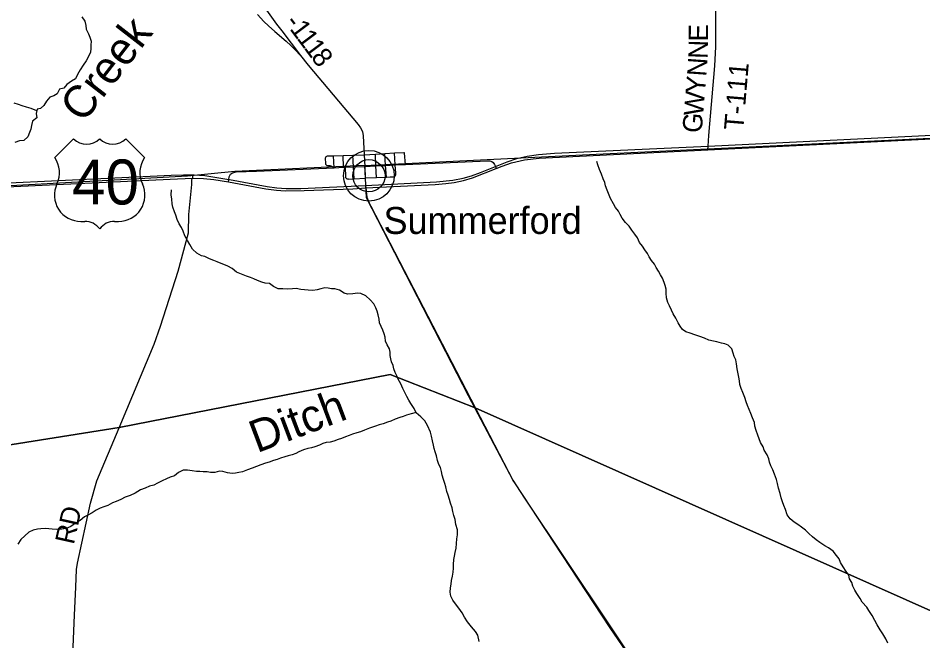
# Model space of a CAD drawing. Extents: x 0 to 36.5, y 0 to 25.3.
# Drawn here: x 3.798 to 6.451, y 15.97 to 17.796 of the extents above; entities that cross this region are included whole.
import ezdxf

# ---------------------------------------------------------------- set-up
doc = ezdxf.new("R2010")
doc.units = 0
for name, color, linetype in [('DV_X_Township_Line', 7, 'Continuous'), ('GM_X_Major_River', 7, 'Continuous'), ('GM_X_Major_River_Text', 7, 'Continuous'), ('GM_X_Minor_River', 7, 'Continuous'), ('GM_X_Minor_River_Text', 7, 'Continuous'), ('GM_X_Rail_Line', 7, 'Continuous'), ('GM_X_State_Route', 7, 'Continuous'), ('GM_X_Township_Road', 7, 'Continuous'), ('GM_X_Township_Road_Text', 7, 'Continuous'), ('GM_X_Unincorporated', 7, 'Continuous'), ('GM_X_Unincorporated_Location', 7, 'Continuous'), ('GM_X_Unincorporated_Text', 7, 'Continuous'), ('GM_X_US_Location', 7, 'Continuous'), ('GM_X_US_Route', 7, 'Continuous'), ('GM_X_US_Shield', 7, 'Continuous'), ('SH_Data', 7, 'Continuous')]:
    doc.layers.add(name, color=color, linetype=linetype)

msp = doc.modelspace()

# ---------------------------------------------------------------- linework, layer by layer
at = {"layer": 'DV_X_Township_Line'}
msp.add_lwpolyline([(4.5783, 20.9), (3.3366, 20.9), (3.2612, 20.6041), (2.8463, 19.037), (2.6265, 18.2595), (2.5271, 17.8912), (2.5226, 17.8751), (2.5165, 17.8524), (2.5144, 17.8445), (2.4192, 17.4891), (2.3437, 17.2326), (2.3403, 17.2198), (2.1039, 16.2931), (2.4938, 16.3413), (4.0938, 16.595), (4.8891, 16.7511), (5.1383, 16.6527), (6.6079, 15.9978)], dxfattribs=at)
msp.add_lwpolyline([(2.1, 16.2788), (2.1, 14.1), (8.9, 14.1), (8.9, 14.8674), (8.5228, 15.0526), (8.0723, 15.2737), (7.8139, 15.4027), (7.7814, 15.4189), (7.7552, 15.432), (7.703, 15.458), (6.8419, 15.8878), (6.6079, 15.9978), (5.1383, 16.6527), (4.8891, 16.7511), (4.0938, 16.595), (2.4938, 16.3413), (2.1039, 16.2931)], close=True, dxfattribs=at)
at = {"layer": 'GM_X_Major_River'}
msp.add_lwpolyline([(3.9844, 17.7994), (3.993, 17.7864), (3.9959, 17.7738), (3.9973, 17.7632), (4.0036, 17.7498), (4.0081, 17.7399), (4.0122, 17.7281), (4.0113, 17.716), (4.0108, 17.7065), (4.0096, 17.6962), (4.0042, 17.6833), (3.9972, 17.6701), (3.988, 17.6576), (3.9795, 17.644), (3.9722, 17.6304), (3.966, 17.6179), (3.9538, 17.6104), (3.9408, 17.601), (3.9316, 17.5905), (3.9194, 17.5872), (3.9117, 17.5732), (3.9022, 17.5679), (3.8908, 17.5635), (3.8804, 17.5522), (3.8731, 17.5397), (3.8632, 17.5306), (3.8533, 17.5284), (3.8505, 17.5163), (3.8527, 17.5034), (3.84, 17.4932), (3.8369, 17.4807), (3.8349, 17.4701), (3.8306, 17.4602), (3.826, 17.4477), (3.8145, 17.4364), (3.8012, 17.4362), (3.7883, 17.4313)], dxfattribs=at)
at = {"layer": 'GM_X_Minor_River'}
for points in [[(3.8523, 17.524), (3.8362, 17.5301), (3.8222, 17.534), (3.8097, 17.5383), (3.7991, 17.5422), (3.7859, 17.5465)], [(6.0244, 16.4315), (6.0214, 16.4425), (6.0155, 16.4586), (6.011, 16.4708), (6.0054, 16.4826), (6.0017, 16.4936), (5.9988, 16.5039), (5.9943, 16.515), (5.9857, 16.5287), (5.9828, 16.5386), (5.9753, 16.5513), (5.9708, 16.5619), (5.9675, 16.573), (5.9619, 16.5867), (5.9582, 16.5997), (5.9568, 16.6096), (5.9512, 16.6241), (5.9468, 16.6359), (5.942, 16.6485), (5.9364, 16.6603), (5.933, 16.671), (5.9286, 16.6832), (5.923, 16.6977), (5.9182, 16.7099), (5.9145, 16.7217), (5.9131, 16.7323), (5.9113, 16.743), (5.9087, 16.7571), (5.9069, 16.7677), (5.9044, 16.7822), (5.9026, 16.7936), (5.8978, 16.8035), (5.8948, 16.8134), (5.8911, 16.8264), (5.8798, 16.8368), (5.87, 16.8403), (5.8605, 16.8426), (5.8472, 16.8462), (5.8374, 16.8489), (5.8237, 16.8517), (5.8109, 16.8571), (5.7968, 16.8622), (5.7824, 16.8669), (5.7684, 16.8719), (5.7559, 16.8758), (5.7457, 16.8828), (5.7397, 16.8927), (5.7338, 16.9023), (5.727, 16.9156), (5.7184, 16.9286), (5.7143, 16.9393), (5.708, 16.9519), (5.7035, 16.9622), (5.6991, 16.9755), (5.6984, 16.9892), (5.6978, 17.001), (5.6956, 17.0113), (5.6923, 17.0208), (5.6871, 17.0331), (5.6814, 17.043), (5.6755, 17.0537), (5.6687, 17.064), (5.6635, 17.0743), (5.6552, 17.0854), (5.6485, 17.0961), (5.6433, 17.1057), (5.6358, 17.1164), (5.6286, 17.1267), (5.62, 17.1378), (5.614, 17.1512), (5.6065, 17.1619), (5.5975, 17.1737), (5.5897, 17.186), (5.5791, 17.1963), (5.5694, 17.2093), (5.563, 17.2197), (5.5585, 17.23), (5.5499, 17.2403), (5.5435, 17.251), (5.5353, 17.2667), (5.5308, 17.2766), (5.5249, 17.2911), (5.5204, 17.3037), (5.5179, 17.3136), (5.513, 17.3243), (5.5086, 17.3376), (5.5026, 17.3517), (5.4974, 17.3655), (5.4952, 17.375)], [(4.3813, 17.081), (4.3713, 17.0849), (4.3592, 17.0896), (4.3456, 17.0962), (4.3354, 17.0989), (4.3218, 17.1062), (4.309, 17.1185), (4.3008, 17.1315), (4.2948, 17.1437), (4.287, 17.157), (4.2814, 17.1708), (4.277, 17.1814), (4.2699, 17.1929), (4.2643, 17.2047), (4.2602, 17.2181), (4.2558, 17.228), (4.2517, 17.2413), (4.2495, 17.2512), (4.2485, 17.2645), (4.2467, 17.2774), (4.2476, 17.2919)], [(4.637, 16.9988), (4.6267, 17), (4.6134, 17.0024), (4.602, 17.0022), (4.5872, 17.0011), (4.5735, 17.0016), (4.5602, 17.0018), (4.5466, 17.0083), (4.5353, 17.0172), (4.522, 17.0188), (4.5125, 17.0212), (4.4993, 17.0266), (4.4891, 17.0309), (4.4789, 17.0355), (4.4671, 17.0394), (4.4527, 17.0453), (4.438, 17.0511), (4.4251, 17.0615), (4.413, 17.0684), (4.3813, 17.081)], [(5.1495, 15.9675), (5.1458, 15.9869), (5.1387, 15.9976), (5.127, 16.0114), (5.1153, 16.0256), (5.1071, 16.0389), (5.1, 16.0515), (5.0899, 16.0653), (5.0831, 16.0748), (5.0726, 16.089), (5.0662, 16.1008), (5.0644, 16.1122), (5.0657, 16.1248), (5.0673, 16.1358), (5.0689, 16.1464), (5.0717, 16.1593), (5.0733, 16.1711), (5.0742, 16.1832), (5.0747, 16.1935), (5.0759, 16.2079), (5.0775, 16.2178), (5.0795, 16.2291), (5.0819, 16.242), (5.0832, 16.255), (5.0841, 16.2686), (5.0861, 16.2804), (5.0862, 16.2956), (5.0818, 16.3108), (5.0789, 16.3257), (5.0759, 16.3371), (5.073, 16.3493), (5.0701, 16.3596), (5.066, 16.3737), (5.0623, 16.3847), (5.0586, 16.3965), (5.0553, 16.4076), (5.0516, 16.4217), (5.0487, 16.4316), (5.045, 16.4426), (5.0417, 16.456), (5.0395, 16.4662), (5.0365, 16.4777), (5.0317, 16.4872), (5.028, 16.4986), (5.0243, 16.512), (5.0206, 16.5238), (5.018, 16.5337), (5.0155, 16.544), (5.0129, 16.5558), (5.0096, 16.5702), (5.0067, 16.5821), (4.9985, 16.6011), (4.9903, 16.6145), (4.9786, 16.6268), (4.9654, 16.6379), (4.9587, 16.6513), (4.9493, 16.6658), (4.9433, 16.6757), (4.9373, 16.6864), (4.9329, 16.696), (4.9262, 16.7093), (4.9202, 16.723), (4.9123, 16.7368), (4.9079, 16.7471), (4.9038, 16.757), (4.8997, 16.7673), (4.8975, 16.7768), (4.8927, 16.7875), (4.8908, 16.797), (4.8887, 16.8066), (4.8887, 16.8161), (4.8869, 16.8256), (4.8798, 16.8374), (4.8753, 16.8481), (4.8743, 16.8603), (4.8714, 16.8698), (4.8677, 16.8805), (4.8628, 16.8912), (4.8572, 16.9022), (4.8562, 16.9125), (4.8536, 16.9258), (4.8503, 16.9361), (4.8462, 16.9461), (4.8406, 16.9579), (4.8297, 16.9701), (4.8173, 16.9813), (4.8025, 16.9879), (4.7927, 16.9895), (4.779, 16.9869), (4.7634, 16.9859), (4.7535, 16.9891), (4.7403, 16.9979), (4.7263, 17.0015), (4.7168, 17.0023), (4.7069, 17.0043), (4.697, 17.0047), (4.6852, 17.0014), (4.6746, 16.9989), (4.662, 16.9974), (4.648, 16.998), (4.637, 16.9988)], [(4.9646, 16.6396), (4.9502, 16.6354), (4.9365, 16.6317), (4.9269, 16.6276), (4.9167, 16.6246), (4.9033, 16.6194), (4.8907, 16.6138), (4.8808, 16.6109), (4.8679, 16.6061), (4.8568, 16.6031), (4.8461, 16.599), (4.8286, 16.5931), (4.8134, 16.5879), (4.8019, 16.5831), (4.7905, 16.5794), (4.7787, 16.5753), (4.7684, 16.5716), (4.7577, 16.5679), (4.7459, 16.5634), (4.7364, 16.5601), (4.7234, 16.5552), (4.7124, 16.5527), (4.701, 16.5513), (4.6911, 16.5483), (4.6811, 16.5434), (4.6678, 16.539), (4.6579, 16.536), (4.6472, 16.5335), (4.635, 16.5298), (4.6213, 16.5238), (4.6118, 16.519), (4.6011, 16.5153), (4.59, 16.5119), (4.5798, 16.5097), (4.5668, 16.5057), (4.5569, 16.5016), (4.547, 16.4982), (4.534, 16.4938), (4.5234, 16.4908), (4.5093, 16.486), (4.4967, 16.4812), (4.4837, 16.4764), (4.47, 16.4708), (4.4559, 16.4656), (4.4448, 16.463), (4.4353, 16.4612), (4.4258, 16.4609), (4.4114, 16.4629), (4.3981, 16.4661), (4.3883, 16.4669), (4.3744, 16.4632)], [(4.3744, 16.4632), (4.3619, 16.4633), (4.3525, 16.4649), (4.34, 16.4654), (4.3305, 16.4662), (4.321, 16.4659), (4.3081, 16.4679), (4.2945, 16.4707), (4.2812, 16.4704), (4.2675, 16.4637), (4.2564, 16.4536), (4.2434, 16.4495), (4.2324, 16.445), (4.2198, 16.4391), (4.2061, 16.4323), (4.1958, 16.4267), (4.1833, 16.4234), (4.1699, 16.4178), (4.1562, 16.413), (4.141, 16.4029), (4.1265, 16.3958), (4.112, 16.3906), (4.0991, 16.3843), (4.0854, 16.3787), (4.0747, 16.3746), (4.061, 16.3671), (4.0488, 16.3627), (4.0385, 16.3593), (4.0267, 16.3534), (4.0145, 16.3455), (4.0023, 16.3387), (3.9924, 16.3331), (3.9798, 16.323), (3.9656, 16.3144), (3.9519, 16.3046), (3.9389, 16.2994), (3.926, 16.2976), (3.9097, 16.2966), (3.8976, 16.2975), (3.8873, 16.2987), (3.8775, 16.2988), (3.8642, 16.2985), (3.8547, 16.2975), (3.8418, 16.2945), (3.8292, 16.2886), (3.817, 16.278), (3.8059, 16.2667), (3.7963, 16.2531)], [(6.3485, 15.9628), (6.3429, 15.9758), (6.3335, 15.9903), (6.3256, 16.0025), (6.317, 16.0167), (6.3103, 16.0296), (6.3025, 16.0441), (6.2923, 16.0591), (6.2863, 16.069), (6.2732, 16.0835), (6.2668, 16.0939), (6.2574, 16.1088), (6.2518, 16.1187), (6.2459, 16.1305), (6.2425, 16.1412), (6.2358, 16.1519), (6.234, 16.1622), (6.2265, 16.1732), (6.2171, 16.187), (6.2092, 16.1992), (6.2051, 16.2099), (6.1976, 16.2202), (6.1879, 16.2329), (6.1743, 16.2425), (6.1637, 16.2483), (6.1493, 16.2579), (6.1384, 16.2663), (6.1271, 16.2748), (6.1165, 16.2848), (6.1067, 16.2944), (6.095, 16.3036), (6.0841, 16.3113), (6.0739, 16.3182), (6.0614, 16.3274), (6.0528, 16.3389), (6.0484, 16.3545), (6.0435, 16.3663), (6.0391, 16.3774), (6.0354, 16.3892), (6.0325, 16.4018), (6.0273, 16.4174), (6.0244, 16.4315)]]:
    msp.add_lwpolyline(points, dxfattribs=at)
at = {"layer": 'GM_X_Rail_Line'}
for points in [[(4.8132, 17.3633), (5.4924, 17.3965), (6.4721, 17.4436), (7.7613, 17.5038), (8.9, 17.5625)], [(4.8132, 17.3633), (4.4331, 17.3456), (4.2941, 17.3319), (2.916, 17.2571), (2.713, 17.2498), (2.6011, 17.2415), (2.3443, 17.2175)], [(4.8132, 17.3633), (4.8184, 17.2699), (5.1178, 16.6892), (5.2481, 16.4408), (5.283, 16.3883), (5.6533, 15.8339), (5.9752, 15.3666), (6.1855, 15.065), (6.3543, 14.8564), (6.3992, 14.8058), (6.6962, 14.5011), (6.7726, 14.421), (6.8941, 14.2837), (7.0545, 14.1)]]:
    msp.add_lwpolyline(points, dxfattribs=at)
at = {"layer": 'GM_X_State_Route'}
msp.add_line((4.832, 17.2439), (5.1386, 16.6522), dxfattribs=at)
for points in [[(4.4998, 17.8062), (4.5187, 17.7859), (4.5321, 17.7729), (4.5503, 17.7566), (4.5838, 17.7283), (4.5974, 17.7156), (4.6104, 17.7023), (4.6253, 17.6855), (4.6484, 17.6579)], [(4.6484, 17.6579), (4.7944, 17.4839), (4.8017, 17.4739), (4.8074, 17.4629), (4.8099, 17.4507), (4.8129, 17.3949), (4.8142, 17.361), (4.8156, 17.3271), (4.8157, 17.3263), (4.8166, 17.3051), (4.8169, 17.2984)], [(4.8169, 17.2984), (4.8203, 17.2711), (4.8269, 17.2537), (4.832, 17.2439)], [(5.1386, 16.6522), (5.2353, 16.4655), (5.2509, 16.4373)], [(5.2509, 16.4373), (5.2534, 16.4329), (5.5332, 16.0079), (5.5924, 15.9207), (5.7648, 15.6702), (6.0961, 15.1927)]]:
    msp.add_lwpolyline(points, dxfattribs=at)
at = {"layer": 'GM_X_Township_Road'}
for p, q in [((5.8207, 17.4095), (5.8211, 17.4202)), ((4.723, 17.3921), (4.7506, 17.3929)), ((4.7244, 17.3568), (4.723, 17.3921)), ((4.7506, 17.3929), (4.7793, 17.3939)), ((4.7517, 17.3581), (4.7506, 17.3929)), ((4.7793, 17.3939), (4.8129, 17.3949)), ((4.7815, 17.3595), (4.7793, 17.3939)), ((4.8129, 17.3949), (4.8454, 17.3969)), ((4.8454, 17.3969), (4.8732, 17.3989)), ((4.8471, 17.3625), (4.8454, 17.3969)), ((4.8732, 17.3989), (4.9018, 17.4003)), ((4.8754, 17.3638), (4.8732, 17.3989)), ((4.9036, 17.3651), (4.9018, 17.4003)), ((4.7244, 17.3568), (4.7517, 17.3581)), ((4.757, 17.3583), (4.7815, 17.3595)), ((4.7815, 17.3595), (4.8142, 17.361)), ((4.7831, 17.3247), (4.7815, 17.3595)), ((4.8142, 17.361), (4.8471, 17.3625)), ((4.8471, 17.3625), (4.8754, 17.3638)), ((4.8488, 17.3282), (4.8471, 17.3625)), ((4.8754, 17.3638), (4.9036, 17.3651)), ((4.8775, 17.3294), (4.8754, 17.3638)), ((4.9036, 17.3651), (4.9334, 17.3665)), ((5.1972, 17.3602), (5.1992, 17.3544)), ((4.8488, 17.3282), (4.8775, 17.3294)), ((4.4141, 17.3151), (4.4153, 17.3226)), ((4.7831, 17.3247), (4.8157, 17.3263)), ((4.8156, 17.3271), (4.8488, 17.3282))]:
    msp.add_line(p, q, dxfattribs=at)
for points in [[(5.8435, 17.781), (5.8426, 17.9125), (5.8425, 17.9325), (5.8418, 18.0956), (5.8415, 18.1092)], [(4.5214, 17.826), (4.5558, 17.7774), (4.5631, 17.7678), (4.5707, 17.7584), (4.6253, 17.6855)], [(5.8211, 17.4202), (5.8233, 17.4516), (5.8408, 17.6555), (5.842, 17.6741), (5.8434, 17.7113), (5.8437, 17.7529), (5.8435, 17.781)], [(4.7244, 17.3568), (4.7161, 17.3611), (4.7125, 17.362), (4.7059, 17.362), (4.7035, 17.3628), (4.7017, 17.364), (4.7002, 17.3666), (4.6998, 17.3694), (4.6993, 17.3851), (4.7001, 17.3876), (4.7014, 17.3896), (4.703, 17.3907), (4.7053, 17.3914), (4.723, 17.3921)], [(4.9018, 17.4003), (4.9289, 17.4016), (4.9302, 17.4011)], [(4.9334, 17.3665), (4.931, 17.4), (4.9302, 17.4011)], [(4.4153, 17.3226), (4.4165, 17.3303), (4.4207, 17.3382), (4.4264, 17.3424), (4.4368, 17.3448), (4.4964, 17.3464), (4.7244, 17.3568)], [(4.7517, 17.3581), (4.7524, 17.3581), (4.757, 17.3583)], [(4.757, 17.3583), (4.7576, 17.3301), (4.758, 17.3285), (4.7589, 17.3269), (4.7604, 17.3257), (4.7619, 17.3248), (4.7655, 17.3242), (4.7677, 17.3238), (4.7831, 17.3247)], [(4.8775, 17.3294), (4.8892, 17.3302), (4.8929, 17.3303), (4.8993, 17.3304), (4.9012, 17.3308), (4.9027, 17.3317), (4.9039, 17.3329), (4.9047, 17.3347), (4.9049, 17.3364), (4.905, 17.3406), (4.9036, 17.3651)], [(4.9334, 17.3665), (5.1746, 17.3775), (5.1808, 17.377), (5.1866, 17.3751), (5.1905, 17.3724), (5.195, 17.3662), (5.1972, 17.3602)], [(4.3091, 17.326), (4.3101, 17.3282), (4.3104, 17.3362)], [(4.094, 16.5944), (4.197, 16.8395), (4.2156, 16.8921), (4.2666, 17.0536), (4.2973, 17.1659), (4.2981, 17.2199), (4.3075, 17.3079), (4.3074, 17.322), (4.3091, 17.326)], [(3.9631, 16.0451), (3.9665, 16.127), (3.9691, 16.1795), (3.9715, 16.198), (4.0103, 16.3736), (4.0288, 16.4392), (4.094, 16.5944)], [(3.9119, 14.9811), (3.9167, 15.0093), (3.9193, 15.0336), (3.9198, 15.1204), (3.9396, 15.4848), (3.9631, 16.0451)]]:
    msp.add_lwpolyline(points, dxfattribs=at)
at = {"layer": 'GM_X_Unincorporated'}
for radius in [0.0744, 0.0472]:
    msp.add_circle((4.8264, 17.3334), radius, dxfattribs=at)
at = {"layer": 'GM_X_Unincorporated_Location'}
msp.add_line((4.8264, 17.3334), (4.8264, 17.3334), dxfattribs=at)
at = {"layer": 'GM_X_US_Route'}
for points in [[(5.2027, 17.3625), (5.2321, 17.3745), (5.2604, 17.3838), (5.2906, 17.3909), (5.3234, 17.3959), (5.3708, 17.3992), (5.8211, 17.4202), (6.7167, 17.464)], [(5.1992, 17.3544), (5.2169, 17.3614), (5.2446, 17.3708), (5.2826, 17.3799), (5.3257, 17.3854), (5.8207, 17.4095), (6.7161, 17.4531)], [(4.4173, 17.3222), (4.5279, 17.3016), (4.5562, 17.2978), (4.5835, 17.2959), (4.6269, 17.296), (4.8166, 17.3051), (5.0243, 17.3152), (5.0728, 17.32), (5.1032, 17.3261), (5.127, 17.333), (5.1532, 17.3425), (5.1972, 17.3602), (5.2027, 17.3625)], [(2.3439, 17.2321), (2.6041, 17.2573), (2.666, 17.2624), (3.5847, 17.3036), (4.2468, 17.3347)], [(4.2468, 17.3347), (4.2827, 17.3364), (4.3104, 17.3362), (4.3137, 17.3362), (4.3447, 17.3338), (4.4153, 17.3226), (4.4173, 17.3222)], [(4.4141, 17.3151), (4.5237, 17.2954), (4.5556, 17.2912), (4.5803, 17.2893), (4.6362, 17.2897), (4.7788, 17.2955), (4.8169, 17.2984), (5.0206, 17.308), (5.0515, 17.3104), (5.0762, 17.3137), (5.1039, 17.3195), (5.1303, 17.3273), (5.1992, 17.3544)], [(2.3405, 17.2192), (2.6107, 17.2468), (2.6789, 17.2516), (3.5758, 17.292), (4.2432, 17.3229)], [(4.2432, 17.3229), (4.3091, 17.326), (4.3411, 17.3257), (4.372, 17.3227), (4.4141, 17.3151)]]:
    msp.add_lwpolyline(points, dxfattribs=at)
at = {"layer": 'GM_X_US_Shield'}
for p, q in [((3.9599, 17.4414), (3.905, 17.3865)), ((4.1686, 17.3865), (4.1137, 17.4414)), ((3.9819, 17.1997), (3.9929, 17.1997)), ((4.0807, 17.1997), (4.0917, 17.1997))]:
    msp.add_line(p, q, dxfattribs=at)
for centre, radius, start, end in [((3.9983, 17.4807), 0.0549, 225.573, 314.427), ((4.0752, 17.4807), 0.0549, 225.573, 314.427), ((3.842, 17.3424), 0.0769, 334.5471, 35.0009), ((4.2316, 17.3424), 0.0769, 144.9991, 205.4529), ((3.981, 17.2766), 0.0769, 154.8319, 270.6383), ((4.0926, 17.2766), 0.0769, 269.3617, 25.1681), ((3.9929, 17.1448), 0.0549, 36.8699, 90), ((4.0807, 17.1448), 0.0549, 90, 143.1301)]:
    msp.add_arc(centre, radius, start, end, dxfattribs=at)
at = {"layer": 'SH_Data'}
msp.add_line((4.832, 17.2439), (5.1386, 16.6522), dxfattribs=at)
for points in [[(4.4998, 17.8062), (4.5187, 17.7859), (4.5321, 17.7729), (4.5503, 17.7566), (4.5838, 17.7283), (4.5974, 17.7156), (4.6104, 17.7023), (4.6253, 17.6855), (4.6484, 17.6579)], [(4.6484, 17.6579), (4.7944, 17.4839), (4.8017, 17.4739), (4.8074, 17.4629), (4.8099, 17.4507), (4.8129, 17.3949), (4.8142, 17.361), (4.8156, 17.3271), (4.8157, 17.3263), (4.8166, 17.3051), (4.8169, 17.2984)], [(4.8169, 17.2984), (4.8203, 17.2711), (4.8269, 17.2537), (4.832, 17.2439)], [(5.1386, 16.6522), (5.2353, 16.4655), (5.2509, 16.4373)], [(5.2509, 16.4373), (5.2534, 16.4329), (5.5332, 16.0079), (5.5924, 15.9207), (5.7648, 15.6702), (6.0961, 15.1927)]]:
    msp.add_lwpolyline(points, dxfattribs=at)

# ---------------------------------------------------------------- texts
at = {"layer": 'GM_X_Major_River_Text'}
msp.add_text('Creek', height=0.09475, rotation=52.1941, dxfattribs=at).set_placement((3.9885, 17.4849))
at = {"layer": 'GM_X_Minor_River_Text'}
msp.add_text('Ditch', height=0.0947, rotation=20.6787, dxfattribs=at).set_placement((4.4981, 16.5197))
at = {"layer": 'GM_X_Township_Road_Text'}
for s, height, rotation, p in [('-', 0.0568, 307.3557, (4.5781, 17.7825)), ('1', 0.0568, 306.9125, (4.5921, 17.7642)), ('1', 0.0568, 306.8288, (4.6129, 17.7364)), ('E', 0.0568, 89.8947, (5.821, 17.7274)), ('1', 0.0568, 306.8269, (4.6337, 17.7086)), ('8', 0.0568, 306.8269, (4.6546, 17.6808)), ('N', 0.0568, 88.266, (5.8195, 17.6757)), ('N', 0.0568, 85.9482, (5.8158, 17.6233)), ('T-111', 0.05682, 85.2358, (5.9242, 17.4655)), ('Y', 0.0568, 85.2589, (5.8116, 17.5727)), ('W', 0.0568, 85.2359, (5.8062, 17.5071)), ('G', 0.0568, 85.237, (5.802, 17.4572)), ('RD', 0.05682, 77.5259, (3.9608, 16.2502))]:
    msp.add_text(s, height=height, rotation=rotation, dxfattribs=at).set_placement(p)
at = {"layer": 'GM_X_Unincorporated_Text'}
msp.add_text('Summerford', height=0.07898, rotation=0, dxfattribs=at).set_placement((4.8693, 17.1628))
at = {"layer": 'GM_X_US_Location'}
for s in ['0', '/']:
    msp.add_text(s, height=0.000189, dxfattribs=at).set_placement((4.0367, 17.314))
msp.add_text('40', height=0.000189, rotation=0, dxfattribs=at).set_placement((3.9976, 17.2748))
at = {"layer": 'GM_X_US_Shield'}
msp.add_text('40', height=0.13184, dxfattribs=at).set_placement((3.9559, 17.2492))

doc.saveas('drawing.dxf')
